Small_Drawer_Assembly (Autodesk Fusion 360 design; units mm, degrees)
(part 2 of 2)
sketch "Sketch6" plane through (0, 0, 13) normal (0, 0, -1) x axis (1, 0, 0)
  line L1 (31.3, 0) -> (0.5, 0)
  line L2 (31.3, 13) -> (31.3, 0)
  line L3 (0.5, 13) -> (31.3, 13)
  line L4 (0.5, 0) -> (0.5, 13)
  line L5 (31.3, 13) -> (0.5, 13)
  line L6 (31.3, 12.2) -> (31.3, 13)
  line L7 (0.5, 12.2) -> (31.3, 12.2)
  line L8 (0.5, 13) -> (0.5, 12.2)
  point P5 (0.5, 13)
  point P6 (0.5, 13)
  point P9 (0.5, 12.2)
  horizontal L5
  vertical L6
  horizontal L7
  vertical L8
  coincident P5 P6
  dimension "d37_3" distance P6 P9 = 0.8
extrude "Extrude7" add sketch "Sketch6" profile of L2 L3 L4 L5 L6 L7 L8 along normal blind 13 named "d38_4"
sketch "Sketch8" plane through (0, 0, 13) normal (0, 0, -1) x axis (1, 0, 0)
  line L1 (0.5, 12.2) -> (31.3, 12.2)
  line L2 (0.5, 0) -> (0.5, 12.2)
  line L3 (31.3, 0) -> (0.5, 0)
  line L4 (31.3, 12.2) -> (31.3, 0)
  line L5 (0.5, 0) -> (1.3, 0)
  line L6 (0.5, 12.2) -> (0.5, 0)
  line L7 (1.3, 12.2) -> (0.5, 12.2)
  line L8 (1.3, 0) -> (1.3, 12.2)
  line L9 (30.5, 0) -> (31.3, 0)
  line L10 (30.5, 12.2) -> (30.5, 0)
  line L11 (31.3, 12.2) -> (30.5, 12.2)
  line L12 (31.3, 0) -> (31.3, 12.2)
  point P3 (0.5, 12.2)
  point P8 (0.5, 12.2)
  point P6 (1.3, 0)
  point P12 (30.5, 12.2)
  point P5 (31.3, 0)
  point P10 (31.3, 0)
  point P13 (31.3, 12.2)
  point P9 (1.3, 12.2)
  horizontal L5
  vertical L6
  horizontal L7
  vertical L8
  coincident P3 P8
  coincident L3 P6
  horizontal L9
  vertical L10
  horizontal L11
  vertical L12
  coincident L1 P12
  coincident P5 P10
  dimension "d45_3" distance P12 P13 = 0.8
  dimension "d46_3" distance P8 P9 = 0.8
extrude "Extrude9" add sketch "Sketch8" along normal blind 13 named "d47_4"
fillet "Fillet2" radius 4 named "d49_4"
chamfer "Chamfer1" distance 3 named "d50_4"
fillet "Fillet3" radius 2 named "d51_4"
fillet "Fillet4" radius 2 named "d52_4"
sketch "Sketch1" plane through (0, 0, 0) normal (0, 0, 1) x axis (1, 0, 0)
  line L1 (31.8, 0) -> (0, 0)
  line L2 (31.8, 80) -> (31.8, 0)
  line L3 (0, 80) -> (31.8, 80)
  line L4 (0, 0) -> (0, 80)
  point P1 (0, 0)
  point P2 (0, 0)
  point P3 (31.8, 0)
  point P4 (31.8, 80)
  horizontal L1
  vertical L2
  horizontal L3
  vertical L4
  coincident P1 P2
  dimension "d1_5" distance P2 P3 = 31.8
  dimension "d2_5" distance P3 P4 = 80
extrude "Extrude1" new body sketch "Sketch1" along normal blind 26.2 named "d3_5"
shell "Shell1" innerThickness 0.8 named "d5_5"
work_plane "WorkPlane1" AlongDistance -18.4 named "d6_5"
sketch "Sketch3" plane through (0, 80, 0) normal (0, 1, 0) x axis (-1, 0, 0)
  line L1 (0, 0) -> (-31.8, 0)
  line L2 (0, 26.2) -> (0, 0)
  line L3 (-31.8, 26.2) -> (0, 26.2)
  line L4 (-31.8, 0) -> (-31.8, 26.2)
  line L5 (-15.9, 0) -> (-15.9, 26.2)
  line L6 (-27.55, 28.45) -> (-27.55, 27.45)
  line L7 (-23.3, 29.7) -> (-26.3, 29.7)
  line L8 (-22.05, 27.45) -> (-22.05, 28.45)
  line L9 (-20.8, 26.2) -> (-28.8, 26.2)
  line L10 (-8.5, 29.7) -> (-5.5, 29.7)
  line L11 (-4.25, 28.45) -> (-4.25, 27.45)
  line L12 (-11, 26.2) -> (-3, 26.2)
  line L13 (-9.75, 27.45) -> (-9.75, 28.45)
  arc A1 centre (-28.8, 27.45) radius 1.25 clockwise from (-27.55, 27.45) to (-28.8, 26.2)
  arc A2 centre (-26.3, 28.45) radius 1.25 clockwise from (-27.55, 28.45) to (-26.3, 29.7)
  arc A3 centre (-23.3, 28.45) radius 1.25 clockwise from (-23.3, 29.7) to (-22.05, 28.45)
  arc A4 centre (-20.8, 27.45) radius 1.25 clockwise from (-20.8, 26.2) to (-22.05, 27.45)
  arc A5 centre (-5.5, 28.45) radius 1.25 clockwise from (-5.5, 29.7) to (-4.25, 28.45)
  arc A6 centre (-11, 27.45) radius 1.25 clockwise from (-9.75, 27.45) to (-11, 26.2)
  arc A7 centre (-3, 27.45) radius 1.25 clockwise from (-3, 26.2) to (-4.25, 27.45)
  arc A8 centre (-8.5, 28.45) radius 1.25 clockwise from (-9.75, 28.45) to (-8.5, 29.7)
  point P10 (-15.9, 26.2)
  point P11 (-15.9, 0)
  point P20 (-24.8, 29.7)
  point P12 (-27.55, 27.45)
  point P27 (-4.25, 27.45)
  point P13 (-27.55, 28.45)
  point P21 (-4.25, 28.45)
  point P14 (-26.3, 29.7)
  point P28 (-5.5, 29.7)
  point P15 (-23.3, 29.7)
  point P26 (-8.5, 29.7)
  point P16 (-22.05, 28.45)
  point P23 (-9.75, 28.45)
  point P17 (-22.05, 27.45)
  point P22 (-9.75, 27.45)
  point P18 (-28.8, 26.2)
  point P30 (-3, 26.2)
  point P19 (-20.8, 26.2)
  point P29 (-11, 26.2)
  point P31 (-7, 29.7)
  midpoint L3 P10
  perpendicular L3 L5
  coincident L1 P11
  horizontal L7
  tangent L7 A2
  tangent L6 A2
  tangent L6 A1
  tangent L7 A3
  tangent L8 A3
  tangent L8 A4
  tangent L9 A4
  tangent L9 A1
  equal A1 A2
  equal A2 A3
  equal A3 A4
  collinear L3 L9
  vertical L8
  vertical L6
  midpoint L7 P20
  symmetric L5 P12 P27
  symmetric L5 P13 P21
  symmetric L5 P14 P28
  symmetric L5 P15 P26
  symmetric L5 P16 P23
  symmetric L5 P17 P22
  symmetric L5 P18 P30
  symmetric L5 P19 P29
  symmetric L5 P20 P31
  symmetric L5 A1 A7
  symmetric L5 A2 A5
  symmetric L5 A3 A8
  symmetric L5 A4 A6
  dimension "d18_4" distance L4 P20 = 7
  dimension "d19_5" distance L7 L9 = 3.5
  dimension "d20_4" distance L6 L8 = 5.5
  dimension "d21_5" radius A1 = 1.25
extrude "Extrude3" add sketch "Sketch3" profile of L3 A1 A2 A3 A4 L6 L7 L8 L9 A5 L10 A6 A7 L11 L12 A8 L13 against normal blind 0.8 named "d22_5"
sketch "Sketch4" plane through (31.8, 0, 0) normal (1, 0, 0) x axis (0, 1, 0)
  line L1 (80, 0) -> (0, 0)
  line L2 (80, 26.2) -> (80, 0)
  line L3 (0, 26.2) -> (80, 26.2)
  line L4 (0, 0) -> (0, 26.2)
  line L5 (10.1071, 17) -> (0.9071, 26.2)
  line L6 (7.8528, 26.2) -> (0.9071, 26.2)
  line L7 (69.7311, 17) -> (10.1071, 17)
  line L8 (78.9311, 26.2) -> (69.7311, 17)
  line L9 (0.9071, 26.2) -> (78.9311, 26.2)
  point P6 (0.9071, 26.2)
  point P10 (78.9311, 26.2)
  horizontal L6
  coincident L3 P6
  horizontal L7
  coincident L3 P10
  dimension "d24_5" angle L5 L6 = 45
  dimension "d25_5" angle L7 L8 = 135
  dimension "d26_5" distance L1 L7 = 17
extrude "Extrude4" cut sketch "Sketch4" profile of L3 L5 L7 L8 L9 against normal blind 31.8 named "d27_5"
extrude "Extrude5" add of existing geometry blind 0.4 named "d29_5"
sketch "Sketch5" plane through (0, 0, 0) normal (0, -1, 0) x axis (1, 0, 0)
  line L1 (31.8, 0) -> (0, 0)
  line L2 (31.8, 26.2) -> (31.8, 0)
  line L3 (0, 26.2) -> (31.8, 26.2)
  line L4 (0, 0) -> (0, 26.2)
  line L5 (31.3, 13.8) -> (0.5, 13.8)
  line L6 (31.3, 13) -> (31.3, 13.8)
  line L7 (0.5, 13) -> (31.3, 13)
  line L8 (0.5, 13.8) -> (0.5, 13)
  horizontal L5
  vertical L6
  horizontal L7
  vertical L8
  dimension "d31_5" distance L4 L8 = 0.5
  dimension "d32_5" distance L2 L6 = 0.5
  dimension "d33_5" distance L5 L7 = 0.8
  dimension "d34_5" distance L1 L7 = 13
extrude "Extrude6" add sketch "Sketch5" profile of L5 L6 L7 L8 along normal blind 13 named "d35_5"
sketch "Sketch6" plane through (0, 0, 13) normal (0, 0, -1) x axis (1, 0, 0)
  line L1 (31.3, 0) -> (0.5, 0)
  line L2 (31.3, 13) -> (31.3, 0)
  line L3 (0.5, 13) -> (31.3, 13)
  line L4 (0.5, 0) -> (0.5, 13)
  line L5 (31.3, 13) -> (0.5, 13)
  line L6 (31.3, 12.2) -> (31.3, 13)
  line L7 (0.5, 12.2) -> (31.3, 12.2)
  line L8 (0.5, 13) -> (0.5, 12.2)
  point P5 (0.5, 13)
  point P6 (0.5, 13)
  point P9 (0.5, 12.2)
  horizontal L5
  vertical L6
  horizontal L7
  vertical L8
  coincident P5 P6
  dimension "d37_4" distance P6 P9 = 0.8
extrude "Extrude7" add sketch "Sketch6" profile of L2 L3 L4 L5 L6 L7 L8 along normal blind 13 named "d38_5"
sketch "Sketch8" plane through (0, 0, 13) normal (0, 0, -1) x axis (1, 0, 0)
  line L1 (0.5, 12.2) -> (31.3, 12.2)
  line L2 (0.5, 0) -> (0.5, 12.2)
  line L3 (31.3, 0) -> (0.5, 0)
  line L4 (31.3, 12.2) -> (31.3, 0)
  line L5 (0.5, 0) -> (1.3, 0)
  line L6 (0.5, 12.2) -> (0.5, 0)
  line L7 (1.3, 12.2) -> (0.5, 12.2)
  line L8 (1.3, 0) -> (1.3, 12.2)
  line L9 (30.5, 0) -> (31.3, 0)
  line L10 (30.5, 12.2) -> (30.5, 0)
  line L11 (31.3, 12.2) -> (30.5, 12.2)
  line L12 (31.3, 0) -> (31.3, 12.2)
  point P3 (0.5, 12.2)
  point P8 (0.5, 12.2)
  point P6 (1.3, 0)
  point P12 (30.5, 12.2)
  point P5 (31.3, 0)
  point P10 (31.3, 0)
  point P13 (31.3, 12.2)
  point P9 (1.3, 12.2)
  horizontal L5
  vertical L6
  horizontal L7
  vertical L8
  coincident P3 P8
  coincident L3 P6
  horizontal L9
  vertical L10
  horizontal L11
  vertical L12
  coincident L1 P12
  coincident P5 P10
  dimension "d45_4" distance P12 P13 = 0.8
  dimension "d46_4" distance P8 P9 = 0.8
extrude "Extrude9" add sketch "Sketch8" along normal blind 13 named "d47_5"
fillet "Fillet2" radius 4 named "d49_5"
chamfer "Chamfer1" distance 3 named "d50_5"
fillet "Fillet3" radius 2 named "d51_5"
fillet "Fillet4" radius 2 named "d52_5"
sketch "Sketch1" plane through (0, 0, 0) normal (0, 0, 1) x axis (1, 0, 0)
  line L1 (31.8, 0) -> (0, 0)
  line L2 (31.8, 80) -> (31.8, 0)
  line L3 (0, 80) -> (31.8, 80)
  line L4 (0, 0) -> (0, 80)
  point P1 (0, 0)
  point P2 (0, 0)
  point P3 (31.8, 0)
  point P4 (31.8, 80)
  horizontal L1
  vertical L2
  horizontal L3
  vertical L4
  coincident P1 P2
  dimension "d1_6" distance P2 P3 = 31.8
  dimension "d2_6" distance P3 P4 = 80
extrude "Extrude1" new body sketch "Sketch1" along normal blind 26.2 named "d3_6"
shell "Shell1" innerThickness 0.8 named "d5_6"
work_plane "WorkPlane1" AlongDistance -18.4 named "d6_6"
sketch "Sketch3" plane through (0, 80, 0) normal (0, 1, 0) x axis (-1, 0, 0)
  line L1 (0, 0) -> (-31.8, 0)
  line L2 (0, 26.2) -> (0, 0)
  line L3 (-31.8, 26.2) -> (0, 26.2)
  line L4 (-31.8, 0) -> (-31.8, 26.2)
  line L5 (-15.9, 0) -> (-15.9, 26.2)
  line L6 (-27.55, 28.45) -> (-27.55, 27.45)
  line L7 (-23.3, 29.7) -> (-26.3, 29.7)
  line L8 (-22.05, 27.45) -> (-22.05, 28.45)
  line L9 (-20.8, 26.2) -> (-28.8, 26.2)
  line L10 (-8.5, 29.7) -> (-5.5, 29.7)
  line L11 (-4.25, 28.45) -> (-4.25, 27.45)
  line L12 (-11, 26.2) -> (-3, 26.2)
  line L13 (-9.75, 27.45) -> (-9.75, 28.45)
  arc A1 centre (-28.8, 27.45) radius 1.25 clockwise from (-27.55, 27.45) to (-28.8, 26.2)
  arc A2 centre (-26.3, 28.45) radius 1.25 clockwise from (-27.55, 28.45) to (-26.3, 29.7)
  arc A3 centre (-23.3, 28.45) radius 1.25 clockwise from (-23.3, 29.7) to (-22.05, 28.45)
  arc A4 centre (-20.8, 27.45) radius 1.25 clockwise from (-20.8, 26.2) to (-22.05, 27.45)
  arc A5 centre (-5.5, 28.45) radius 1.25 clockwise from (-5.5, 29.7) to (-4.25, 28.45)
  arc A6 centre (-11, 27.45) radius 1.25 clockwise from (-9.75, 27.45) to (-11, 26.2)
  arc A7 centre (-3, 27.45) radius 1.25 clockwise from (-3, 26.2) to (-4.25, 27.45)
  arc A8 centre (-8.5, 28.45) radius 1.25 clockwise from (-9.75, 28.45) to (-8.5, 29.7)
  point P10 (-15.9, 26.2)
  point P11 (-15.9, 0)
  point P20 (-24.8, 29.7)
  point P12 (-27.55, 27.45)
  point P27 (-4.25, 27.45)
  point P13 (-27.55, 28.45)
  point P21 (-4.25, 28.45)
  point P14 (-26.3, 29.7)
  point P28 (-5.5, 29.7)
  point P15 (-23.3, 29.7)
  point P26 (-8.5, 29.7)
  point P16 (-22.05, 28.45)
  point P23 (-9.75, 28.45)
  point P17 (-22.05, 27.45)
  point P22 (-9.75, 27.45)
  point P18 (-28.8, 26.2)
  point P30 (-3, 26.2)
  point P19 (-20.8, 26.2)
  point P29 (-11, 26.2)
  point P31 (-7, 29.7)
  midpoint L3 P10
  perpendicular L3 L5
  coincident L1 P11
  horizontal L7
  tangent L7 A2
  tangent L6 A2
  tangent L6 A1
  tangent L7 A3
  tangent L8 A3
  tangent L8 A4
  tangent L9 A4
  tangent L9 A1
  equal A1 A2
  equal A2 A3
  equal A3 A4
  collinear L3 L9
  vertical L8
  vertical L6
  midpoint L7 P20
  symmetric L5 P12 P27
  symmetric L5 P13 P21
  symmetric L5 P14 P28
  symmetric L5 P15 P26
  symmetric L5 P16 P23
  symmetric L5 P17 P22
  symmetric L5 P18 P30
  symmetric L5 P19 P29
  symmetric L5 P20 P31
  symmetric L5 A1 A7
  symmetric L5 A2 A5
  symmetric L5 A3 A8
  symmetric L5 A4 A6
  dimension "d18_5" distance L4 P20 = 7
  dimension "d19_6" distance L7 L9 = 3.5
  dimension "d20_5" distance L6 L8 = 5.5
  dimension "d21_6" radius A1 = 1.25
extrude "Extrude3" add sketch "Sketch3" profile of L3 A1 A2 A3 A4 L6 L7 L8 L9 A5 L10 A6 A7 L11 L12 A8 L13 against normal blind 0.8 named "d22_6"
sketch "Sketch4" plane through (31.8, 0, 0) normal (1, 0, 0) x axis (0, 1, 0)
  line L1 (80, 0) -> (0, 0)
  line L2 (80, 26.2) -> (80, 0)
  line L3 (0, 26.2) -> (80, 26.2)
  line L4 (0, 0) -> (0, 26.2)
  line L5 (10.1071, 17) -> (0.9071, 26.2)
  line L6 (7.8528, 26.2) -> (0.9071, 26.2)
  line L7 (69.7311, 17) -> (10.1071, 17)
  line L8 (78.9311, 26.2) -> (69.7311, 17)
  line L9 (0.9071, 26.2) -> (78.9311, 26.2)
  point P6 (0.9071, 26.2)
  point P10 (78.9311, 26.2)
  horizontal L6
  coincident L3 P6
  horizontal L7
  coincident L3 P10
  dimension "d24_6" angle L5 L6 = 45
  dimension "d25_6" angle L7 L8 = 135
  dimension "d26_6" distance L1 L7 = 17
extrude "Extrude4" cut sketch "Sketch4" profile of L3 L5 L7 L8 L9 against normal blind 31.8 named "d27_6"
extrude "Extrude5" add of existing geometry blind 0.4 named "d29_6"
sketch "Sketch5" plane through (0, 0, 0) normal (0, -1, 0) x axis (1, 0, 0)
  line L1 (31.8, 0) -> (0, 0)
  line L2 (31.8, 26.2) -> (31.8, 0)
  line L3 (0, 26.2) -> (31.8, 26.2)
  line L4 (0, 0) -> (0, 26.2)
  line L5 (31.3, 13.8) -> (0.5, 13.8)
  line L6 (31.3, 13) -> (31.3, 13.8)
  line L7 (0.5, 13) -> (31.3, 13)
  line L8 (0.5, 13.8) -> (0.5, 13)
  horizontal L5
  vertical L6
  horizontal L7
  vertical L8
  dimension "d31_6" distance L4 L8 = 0.5
  dimension "d32_6" distance L2 L6 = 0.5
  dimension "d33_6" distance L5 L7 = 0.8
  dimension "d34_6" distance L1 L7 = 13
extrude "Extrude6" add sketch "Sketch5" profile of L5 L6 L7 L8 along normal blind 13 named "d35_6"
sketch "Sketch6" plane through (0, 0, 13) normal (0, 0, -1) x axis (1, 0, 0)
  line L1 (31.3, 0) -> (0.5, 0)
  line L2 (31.3, 13) -> (31.3, 0)
  line L3 (0.5, 13) -> (31.3, 13)
  line L4 (0.5, 0) -> (0.5, 13)
  line L5 (31.3, 13) -> (0.5, 13)
  line L6 (31.3, 12.2) -> (31.3, 13)
  line L7 (0.5, 12.2) -> (31.3, 12.2)
  line L8 (0.5, 13) -> (0.5, 12.2)
  point P5 (0.5, 13)
  point P6 (0.5, 13)
  point P9 (0.5, 12.2)
  horizontal L5
  vertical L6
  horizontal L7
  vertical L8
  coincident P5 P6
  dimension "d37_5" distance P6 P9 = 0.8
extrude "Extrude7" add sketch "Sketch6" profile of L2 L3 L4 L5 L6 L7 L8 along normal blind 13 named "d38_6"
sketch "Sketch8" plane through (0, 0, 13) normal (0, 0, -1) x axis (1, 0, 0)
  line L1 (0.5, 12.2) -> (31.3, 12.2)
  line L2 (0.5, 0) -> (0.5, 12.2)
  line L3 (31.3, 0) -> (0.5, 0)
  line L4 (31.3, 12.2) -> (31.3, 0)
  line L5 (0.5, 0) -> (1.3, 0)
  line L6 (0.5, 12.2) -> (0.5, 0)
  line L7 (1.3, 12.2) -> (0.5, 12.2)
  line L8 (1.3, 0) -> (1.3, 12.2)
  line L9 (30.5, 0) -> (31.3, 0)
  line L10 (30.5, 12.2) -> (30.5, 0)
  line L11 (31.3, 12.2) -> (30.5, 12.2)
  line L12 (31.3, 0) -> (31.3, 12.2)
  point P3 (0.5, 12.2)
  point P8 (0.5, 12.2)
  point P6 (1.3, 0)
  point P12 (30.5, 12.2)
  point P5 (31.3, 0)
  point P10 (31.3, 0)
  point P13 (31.3, 12.2)
  point P9 (1.3, 12.2)
  horizontal L5
  vertical L6
  horizontal L7
  vertical L8
  coincident P3 P8
  coincident L3 P6
  horizontal L9
  vertical L10
  horizontal L11
  vertical L12
  coincident L1 P12
  coincident P5 P10
  dimension "d45_5" distance P12 P13 = 0.8
  dimension "d46_5" distance P8 P9 = 0.8
extrude "Extrude9" add sketch "Sketch8" along normal blind 13 named "d47_6"
fillet "Fillet2" radius 4 named "d49_6"
chamfer "Chamfer1" distance 3 named "d50_6"
fillet "Fillet3" radius 2 named "d51_6"
fillet "Fillet4" radius 2 named "d52_6"
sketch "Sketch1" plane through (0, 0, 0) normal (0, 0, 1) x axis (1, 0, 0)
  line L1 (31.8, 0) -> (0, 0)
  line L2 (31.8, 80) -> (31.8, 0)
  line L3 (0, 80) -> (31.8, 80)
  line L4 (0, 0) -> (0, 80)
  point P1 (0, 0)
  point P2 (0, 0)
  point P3 (31.8, 0)
  point P4 (31.8, 80)
  horizontal L1
  vertical L2
  horizontal L3
  vertical L4
  coincident P1 P2
  dimension "d1_7" distance P2 P3 = 31.8
  dimension "d2_7" distance P3 P4 = 80
extrude "Extrude1" new body sketch "Sketch1" along normal blind 26.2 named "d3_7"
shell "Shell1" innerThickness 0.8 named "d5_7"
work_plane "WorkPlane1" AlongDistance -18.4 named "d6_7"
sketch "Sketch3" plane through (0, 80, 0) normal (0, 1, 0) x axis (-1, 0, 0)
  line L1 (0, 0) -> (-31.8, 0)
  line L2 (0, 26.2) -> (0, 0)
  line L3 (-31.8, 26.2) -> (0, 26.2)
  line L4 (-31.8, 0) -> (-31.8, 26.2)
  line L5 (-15.9, 0) -> (-15.9, 26.2)
  line L6 (-27.55, 28.45) -> (-27.55, 27.45)
  line L7 (-23.3, 29.7) -> (-26.3, 29.7)
  line L8 (-22.05, 27.45) -> (-22.05, 28.45)
  line L9 (-20.8, 26.2) -> (-28.8, 26.2)
  line L10 (-8.5, 29.7) -> (-5.5, 29.7)
  line L11 (-4.25, 28.45) -> (-4.25, 27.45)
  line L12 (-11, 26.2) -> (-3, 26.2)
  line L13 (-9.75, 27.45) -> (-9.75, 28.45)
  arc A1 centre (-28.8, 27.45) radius 1.25 clockwise from (-27.55, 27.45) to (-28.8, 26.2)
  arc A2 centre (-26.3, 28.45) radius 1.25 clockwise from (-27.55, 28.45) to (-26.3, 29.7)
  arc A3 centre (-23.3, 28.45) radius 1.25 clockwise from (-23.3, 29.7) to (-22.05, 28.45)
  arc A4 centre (-20.8, 27.45) radius 1.25 clockwise from (-20.8, 26.2) to (-22.05, 27.45)
  arc A5 centre (-5.5, 28.45) radius 1.25 clockwise from (-5.5, 29.7) to (-4.25, 28.45)
  arc A6 centre (-11, 27.45) radius 1.25 clockwise from (-9.75, 27.45) to (-11, 26.2)
  arc A7 centre (-3, 27.45) radius 1.25 clockwise from (-3, 26.2) to (-4.25, 27.45)
  arc A8 centre (-8.5, 28.45) radius 1.25 clockwise from (-9.75, 28.45) to (-8.5, 29.7)
  point P10 (-15.9, 26.2)
  point P11 (-15.9, 0)
  point P20 (-24.8, 29.7)
  point P12 (-27.55, 27.45)
  point P27 (-4.25, 27.45)
  point P13 (-27.55, 28.45)
  point P21 (-4.25, 28.45)
  point P14 (-26.3, 29.7)
  point P28 (-5.5, 29.7)
  point P15 (-23.3, 29.7)
  point P26 (-8.5, 29.7)
  point P16 (-22.05, 28.45)
  point P23 (-9.75, 28.45)
  point P17 (-22.05, 27.45)
  point P22 (-9.75, 27.45)
  point P18 (-28.8, 26.2)
  point P30 (-3, 26.2)
  point P19 (-20.8, 26.2)
  point P29 (-11, 26.2)
  point P31 (-7, 29.7)
  midpoint L3 P10
  perpendicular L3 L5
  coincident L1 P11
  horizontal L7
  tangent L7 A2
  tangent L6 A2
  tangent L6 A1
  tangent L7 A3
  tangent L8 A3
  tangent L8 A4
  tangent L9 A4
  tangent L9 A1
  equal A1 A2
  equal A2 A3
  equal A3 A4
  collinear L3 L9
  vertical L8
  vertical L6
  midpoint L7 P20
  symmetric L5 P12 P27
  symmetric L5 P13 P21
  symmetric L5 P14 P28
  symmetric L5 P15 P26
  symmetric L5 P16 P23
  symmetric L5 P17 P22
  symmetric L5 P18 P30
  symmetric L5 P19 P29
  symmetric L5 P20 P31
  symmetric L5 A1 A7
  symmetric L5 A2 A5
  symmetric L5 A3 A8
  symmetric L5 A4 A6
  dimension "d18_6" distance L4 P20 = 7
  dimension "d19_7" distance L7 L9 = 3.5
  dimension "d20_6" distance L6 L8 = 5.5
  dimension "d21_7" radius A1 = 1.25
extrude "Extrude3" add sketch "Sketch3" profile of L3 A1 A2 A3 A4 L6 L7 L8 L9 A5 L10 A6 A7 L11 L12 A8 L13 against normal blind 0.8 named "d22_7"
sketch "Sketch4" plane through (31.8, 0, 0) normal (1, 0, 0) x axis (0, 1, 0)
  line L1 (80, 0) -> (0, 0)
  line L2 (80, 26.2) -> (80, 0)
  line L3 (0, 26.2) -> (80, 26.2)
  line L4 (0, 0) -> (0, 26.2)
  line L5 (10.1071, 17) -> (0.9071, 26.2)
  line L6 (7.8528, 26.2) -> (0.9071, 26.2)
  line L7 (69.7311, 17) -> (10.1071, 17)
  line L8 (78.9311, 26.2) -> (69.7311, 17)
  line L9 (0.9071, 26.2) -> (78.9311, 26.2)
  point P6 (0.9071, 26.2)
  point P10 (78.9311, 26.2)
  horizontal L6
  coincident L3 P6
  horizontal L7
  coincident L3 P10
  dimension "d24_7" angle L5 L6 = 45
  dimension "d25_7" angle L7 L8 = 135
  dimension "d26_7" distance L1 L7 = 17
extrude "Extrude4" cut sketch "Sketch4" profile of L3 L5 L7 L8 L9 against normal blind 31.8 named "d27_7"
extrude "Extrude5" add of existing geometry blind 0.4 named "d29_7"
sketch "Sketch5" plane through (0, 0, 0) normal (0, -1, 0) x axis (1, 0, 0)
  line L1 (31.8, 0) -> (0, 0)
  line L2 (31.8, 26.2) -> (31.8, 0)
  line L3 (0, 26.2) -> (31.8, 26.2)
  line L4 (0, 0) -> (0, 26.2)
  line L5 (31.3, 13.8) -> (0.5, 13.8)
  line L6 (31.3, 13) -> (31.3, 13.8)
  line L7 (0.5, 13) -> (31.3, 13)
  line L8 (0.5, 13.8) -> (0.5, 13)
  horizontal L5
  vertical L6
  horizontal L7
  vertical L8
  dimension "d31_7" distance L4 L8 = 0.5
  dimension "d32_7" distance L2 L6 = 0.5
  dimension "d33_7" distance L5 L7 = 0.8
  dimension "d34_7" distance L1 L7 = 13
extrude "Extrude6" add sketch "Sketch5" profile of L5 L6 L7 L8 along normal blind 13 named "d35_7"
sketch "Sketch6" plane through (0, 0, 13) normal (0, 0, -1) x axis (1, 0, 0)
  line L1 (31.3, 0) -> (0.5, 0)
  line L2 (31.3, 13) -> (31.3, 0)
  line L3 (0.5, 13) -> (31.3, 13)
  line L4 (0.5, 0) -> (0.5, 13)
  line L5 (31.3, 13) -> (0.5, 13)
  line L6 (31.3, 12.2) -> (31.3, 13)
  line L7 (0.5, 12.2) -> (31.3, 12.2)
  line L8 (0.5, 13) -> (0.5, 12.2)
  point P5 (0.5, 13)
  point P6 (0.5, 13)
  point P9 (0.5, 12.2)
  horizontal L5
  vertical L6
  horizontal L7
  vertical L8
  coincident P5 P6
  dimension "d37_6" distance P6 P9 = 0.8
extrude "Extrude7" add sketch "Sketch6" profile of L2 L3 L4 L5 L6 L7 L8 along normal blind 13 named "d38_7"
sketch "Sketch8" plane through (0, 0, 13) normal (0, 0, -1) x axis (1, 0, 0)
  line L1 (0.5, 12.2) -> (31.3, 12.2)
  line L2 (0.5, 0) -> (0.5, 12.2)
  line L3 (31.3, 0) -> (0.5, 0)
  line L4 (31.3, 12.2) -> (31.3, 0)
  line L5 (0.5, 0) -> (1.3, 0)
  line L6 (0.5, 12.2) -> (0.5, 0)
  line L7 (1.3, 12.2) -> (0.5, 12.2)
  line L8 (1.3, 0) -> (1.3, 12.2)
  line L9 (30.5, 0) -> (31.3, 0)
  line L10 (30.5, 12.2) -> (30.5, 0)
  line L11 (31.3, 12.2) -> (30.5, 12.2)
  line L12 (31.3, 0) -> (31.3, 12.2)
  point P3 (0.5, 12.2)
  point P8 (0.5, 12.2)
  point P6 (1.3, 0)
  point P12 (30.5, 12.2)
  point P5 (31.3, 0)
  point P10 (31.3, 0)
  point P13 (31.3, 12.2)
  point P9 (1.3, 12.2)
  horizontal L5
  vertical L6
  horizontal L7
  vertical L8
  coincident P3 P8
  coincident L3 P6
  horizontal L9
  vertical L10
  horizontal L11
  vertical L12
  coincident L1 P12
  coincident P5 P10
  dimension "d45_6" distance P12 P13 = 0.8
  dimension "d46_6" distance P8 P9 = 0.8
extrude "Extrude9" add sketch "Sketch8" along normal blind 13 named "d47_7"
fillet "Fillet2" radius 4 named "d49_7"
chamfer "Chamfer1" distance 3 named "d50_7"
fillet "Fillet3" radius 2 named "d51_7"
fillet "Fillet4" radius 2 named "d52_7"
position "Position1"
joint "Assemble1" OffsetX 0 OffsetY 0 OffsetZ 0 AngleZ 0 alignAngle 0 alignOffsetX 0 alignOffsetY 0 alignOffsetZ 0
position "Position2"
joint "Assemble3" OffsetX 0 OffsetY 0 OffsetZ 0 AngleZ 0 alignAngle 0 alignOffsetX 0 alignOffsetY 0 alignOffsetZ 0
position "Position3"
joint "Assemble4" OffsetX 0 OffsetY 0 OffsetZ 0 AngleZ 0 alignAngle 0 alignOffsetX 0 alignOffsetY 0 alignOffsetZ 0
position "Position4"
position "Position5"
joint "Assemble6" OffsetX 0 OffsetY 0 OffsetZ 0 AngleZ 0 alignAngle 0 alignOffsetX 0 alignOffsetY 0 alignOffsetZ 0
position "Position6"
joint "Assemble7" OffsetX 0 OffsetY 0 OffsetZ 0 AngleZ 0 alignAngle 0 alignOffsetX 0 alignOffsetY 0 alignOffsetZ 0
position "Position7"
joint "Assemble8" OffsetX 0 OffsetY 0 OffsetZ 0 AngleZ 0 alignAngle 0 alignOffsetX 0 alignOffsetY 0 alignOffsetZ 0
sketch "Sketch6" plane through (0, 0, 0) normal (0, -1, 0) x axis (1, 0, 0)
  line L1 (99.4, 1.2) -> (99.4, 28.2)
  line L2 (67.2, 1.2) -> (99.4, 1.2)
  line L3 (67.2, 28.2) -> (67.2, 1.2)
  line L4 (99.4, 28.2) -> (67.2, 28.2)
  line L5 (199.2, 28.2) -> (199.2, 1.2)
  line L6 (231.4, 28.2) -> (199.2, 28.2)
  line L7 (231.4, 1.2) -> (231.4, 28.2)
  line L8 (199.2, 1.2) -> (231.4, 1.2)
  line L9 (132.4, 1.2) -> (132.4, 28.2)
  line L10 (100.2, 1.2) -> (132.4, 1.2)
  line L11 (100.2, 28.2) -> (100.2, 1.2)
  line L12 (132.4, 28.2) -> (100.2, 28.2)
  line L13 (66.4, 1.2) -> (66.4, 28.2)
  line L14 (34.2, 1.2) -> (66.4, 1.2)
  line L15 (34.2, 28.2) -> (34.2, 1.2)
  line L16 (66.4, 28.2) -> (34.2, 28.2)
  line L17 (166.2, 28.2) -> (166.2, 1.2)
  line L18 (198.4, 28.2) -> (166.2, 28.2)
  line L19 (198.4, 1.2) -> (198.4, 28.2)
  line L20 (166.2, 1.2) -> (198.4, 1.2)
  line L21 (165.4, 1.2) -> (165.4, 28.2)
  line L22 (133.2, 1.2) -> (165.4, 1.2)
  line L23 (133.2, 28.2) -> (133.2, 1.2)
  line L24 (165.4, 28.2) -> (133.2, 28.2)
  line L25 (33.4, 1.2) -> (33.4, 28.2)
  line L26 (1.2, 1.2) -> (33.4, 1.2)
  line L27 (1.2, 28.2) -> (1.2, 1.2)
  line L28 (33.4, 28.2) -> (1.2, 28.2)
  line L29 (232.6, 0) -> (0, 0)
  line L30 (232.6, 38.2) -> (232.6, 0)
  line L31 (0, 38.2) -> (232.6, 38.2)
  line L32 (0, 0) -> (0, 38.2)
  line L33 (232.6, 38.2) -> (0, 38.2)
  line L34 (232.6, 28.2) -> (232.6, 38.2)
  line L35 (0, 28.2) -> (232.6, 28.2)
  line L36 (0, 38.2) -> (0, 28.2)
  point P33 (0, 38.2)
  point P34 (0, 38.2)
  point P37 (0, 28.2)
  horizontal L33
  vertical L34
  horizontal L35
  vertical L36
  coincident P33 P34
  dimension "d269" distance P34 P37 = 10
extrude "Extrude9" new body sketch "Sketch6" profile of L4 L6 L12 L16 L18 L24 L28 L30 L31 L32 L33 L34 L35 L36 along normal blind 2
sketch "Sketch7" plane through (0, -2, 0) normal (0, -1, 0) x axis (1, 0, 0)
  line L1 (232.6, 28.2) -> (0, 28.2)
  line L2 (232.6, 38.2) -> (232.6, 28.2)
  line L3 (0, 38.2) -> (232.6, 38.2)
  line L4 (0, 28.2) -> (0, 38.2)
  line L5 (20, 35.7) -> (15, 35.7)
  line L6 (20, 30.7) -> (20, 35.7)
  line L7 (15, 30.7) -> (20, 30.7)
  line L8 (15, 35.7) -> (15, 30.7)
  line L9 (53, 35.7) -> (48, 35.7)
  line L10 (53, 30.7) -> (53, 35.7)
  line L11 (48, 30.7) -> (53, 30.7)
  line L12 (48, 35.7) -> (48, 30.7)
  line L13 (86, 35.7) -> (81, 35.7)
  line L14 (86, 30.7) -> (86, 35.7)
  line L15 (81, 30.7) -> (86, 30.7)
  line L16 (81, 35.7) -> (81, 30.7)
  line L17 (119, 35.7) -> (114, 35.7)
  line L18 (119, 30.7) -> (119, 35.7)
  line L19 (114, 30.7) -> (119, 30.7)
  line L20 (114, 35.7) -> (114, 30.7)
  line L21 (152, 35.7) -> (147, 35.7)
  line L22 (152, 30.7) -> (152, 35.7)
  line L23 (147, 30.7) -> (152, 30.7)
  line L24 (147, 35.7) -> (147, 30.7)
  line L25 (185, 35.7) -> (180, 35.7)
  line L26 (185, 30.7) -> (185, 35.7)
  line L27 (180, 30.7) -> (185, 30.7)
  line L28 (180, 35.7) -> (180, 30.7)
  line L29 (218, 35.7) -> (213, 35.7)
  line L30 (218, 30.7) -> (218, 35.7)
  line L31 (213, 30.7) -> (218, 30.7)
  line L32 (213, 35.7) -> (213, 30.7)
  point P6 (15, 35.7)
  point P7 (20, 35.7)
  point P9 (15, 30.7)
  point P10 (48, 35.7)
  point P11 (53, 35.7)
  point P13 (48, 30.7)
  point P14 (81, 35.7)
  point P15 (86, 35.7)
  point P17 (81, 30.7)
  point P18 (114, 35.7)
  point P19 (119, 35.7)
  point P21 (114, 30.7)
  point P22 (147, 35.7)
  point P23 (152, 35.7)
  point P25 (147, 30.7)
  point P26 (180, 35.7)
  point P27 (185, 35.7)
  point P29 (180, 30.7)
  point P30 (213, 35.7)
  point P31 (218, 35.7)
  point P33 (213, 30.7)
  horizontal L5
  vertical L6
  horizontal L7
  vertical L8
  horizontal L9
  vertical L10
  horizontal L11
  vertical L12
  horizontal L13
  vertical L14
  horizontal L15
  vertical L16
  horizontal L17
  vertical L18
  horizontal L19
  vertical L20
  horizontal L21
  vertical L22
  horizontal L23
  vertical L24
  horizontal L25
  vertical L26
  horizontal L27
  vertical L28
  horizontal L29
  vertical L30
  horizontal L31
  vertical L32
  dimension "d272" distance P6 P7 = 5
  dimension "d273" distance P6 P9 = 5
  dimension "d274" distance P10 P11 = 5
  dimension "d275" distance P10 P13 = 5
  dimension "d276" distance L6 L12 = 28
  dimension "d277" distance L4 L8 = 15
  dimension "d278" distance P14 P15 = 5
  dimension "d279" distance P14 P17 = 5
  dimension "d280" distance L10 L16 = 28
  dimension "d281" distance P18 P19 = 5
  dimension "d282" distance P18 P21 = 5
  dimension "d283" distance L14 L20 = 28
  dimension "d284" distance P22 P23 = 5
  dimension "d285" distance P22 P25 = 5
  dimension "d286" distance L18 L24 = 28
  dimension "d287" distance P26 P27 = 5
  dimension "d288" distance P26 P29 = 5
  dimension "d289" distance L22 L28 = 28
  dimension "d290" distance P30 P31 = 5
  dimension "d291" distance P30 P33 = 5
  dimension "d292" distance L26 L32 = 28
  dimension "d293" distance L3 L5 = 2.5
  dimension "d294" distance L3 L9 = 2.5
  dimension "d295" distance L3 L13 = 2.5
  dimension "d296" distance L3 L17 = 2.5
  dimension "d297" distance L3 L21 = 2.5
  dimension "d298" distance L3 L25 = 2.5
  dimension "d299" distance L3 L29 = 2.5
extrude "Extrude10" add sketch "Sketch7" profile of L5 L6 L7 L8 L9 L10 L11 L12 L13 L14 L15 L16 L17 L18 L19 L20 L21 L22 L23 L24 L25 L26 L27 L28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 along normal blind 2
position "Position9"
joint "Assemble11" OffsetX 0 OffsetY 0 OffsetZ 0 AngleZ 0 alignAngle 0 alignOffsetX 0 alignOffsetY -22 alignOffsetZ 0
position "Position10"
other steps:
joint_origin "JointOrigin1" OffsetX 0 OffsetY 0 OffsetZ 0 AngleZ 0
joint_origin "JointOrigin3" OffsetX 0 OffsetY 0 OffsetZ 0 AngleZ 0
joint_origin "JointOrigin4" OffsetX 0 OffsetY 0 OffsetZ 0 AngleZ 0
joint_origin "JointOrigin6" OffsetX 0 OffsetY 0 OffsetZ 0 AngleZ 0
joint_origin "JointOrigin7" OffsetX 0 OffsetY 0 OffsetZ 0 AngleZ 0
joint_origin "JointOrigin8" OffsetX 0 OffsetY 0 OffsetZ 0 AngleZ 0
joint_origin "JointOrigin12" OffsetX 0 OffsetY 0 OffsetZ 0 AngleZ 0
create_component "CreateComponent1"
create_component "CreateComponent2"
create_component "CreateComponent3"
create_component "CreateComponent4"
create_component "CreateComponent5"
create_component "CreateComponent6"
create_component "CreateComponent7"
